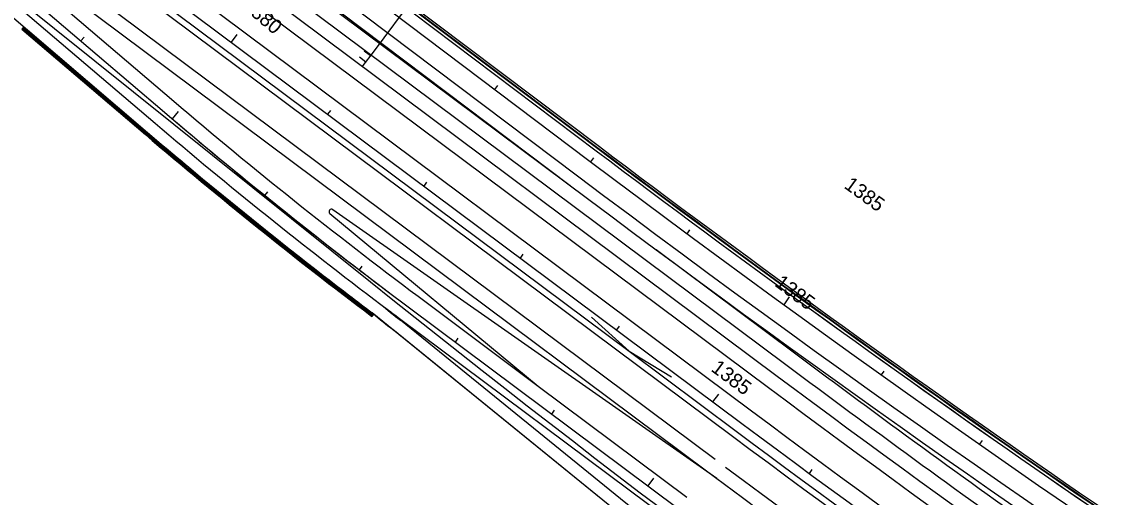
# Model space of a CAD drawing. Extents: x 2338610 to 2351914, y 366540 to 376484.
# Drawn here: x 2344700 to 2345613, y 370482 to 370877 of the extents above; entities that cross this region are included whole.
import ezdxf

# ---------------------------------------------------------------- set-up
doc = ezdxf.new("R2010")
doc.units = 0
for name, color, linetype in [('RD_HC_Cl', 7, 'Continuous'), ('RD_HC_CL_Rel', 7, 'Continuous'), ('RD_PD_Final_LnLine', 7, 'Continuous'), ('RD_PD_Final_TrvlWay', 7, 'Continuous'), ('RD_PD_GR', 7, 'Continuous'), ('RD_PD_MedBWall', 7, 'Continuous'), ('RD_PD_MedGR', 7, 'Continuous'), ('RD_PD_NOISE-WALL-GM', 7, 'Continuous'), ('RD_PD_PaveShd', 7, 'Continuous'), ('RD_PD_WallFill', 7, 'Continuous'), ('TR SN EXTRUDED PANEL SIGNS - GROUND MOUNTED', 7, 'Continuous'), ('TR SN UNASSIGNED 7', 7, 'Continuous')]:
    doc.layers.add(name, color=color, linetype=linetype)

msp = doc.modelspace()

# ---------------------------------------------------------------- linework, layer by layer
at = {"layer": 'RD_HC_Cl'}
for p, q in [((2339299.68, 375020.33), (2345298.75, 370542.85)), ((2344813.13, 371031.79), (2345171.51, 370761.65))]:
    msp.add_line(p, q, dxfattribs=at)
for centre, radius, start, end in [((2352034, 379865.62), 11400.7, 232.99132, 241.72492), ((2352152.85, 379726.19), 11459.16, 233.263715, 239.178507)]:
    msp.add_arc(centre, radius, start, end, dxfattribs=at)
at = {"layer": 'RD_HC_CL_Rel'}
for p, q in [((2344362.05, 371190.8), (2344818.24, 370801.72)), ((2345022.04, 370639.05), (2345245.86, 370471.99))]:
    msp.add_line(p, q, dxfattribs=at)
msp.add_arc((2347422.04, 373854.65), 4012.5, 229.5396, 233.26372, dxfattribs=at)
at = {"layer": 'RD_PD_Final_LnLine'}
for p, q in [((2344195, 371413.02), (2345320.98, 370572.63)), ((2344150.54, 371353.45), (2345276.52, 370513.06)), ((2344330.62, 371189.3), (2344989.66, 370660.63)), ((2344330.62, 371189.3), (2344989.66, 370660.63)), ((2344330.62, 371189.3), (2344989.66, 370660.63)), ((2344330.62, 371189.3), (2344989.66, 370660.63)), ((2344457.72, 371109.21), (2344818.24, 370801.72)), ((2344782.88, 370989.22), (2345328.15, 370582.25)), ((2345022.04, 370639.05), (2345245.86, 370471.99)), ((2345014.86, 370629.43), (2345238.68, 370462.38))]:
    msp.add_line(p, q, dxfattribs=at)
for centre, radius, start, end in [((2347422.04, 373854.65), 4012.5, 229.5396, 232.9704), ((2351872.76, 379241.01), 11000, 231.263715, 239.178507), ((2351872.76, 379241.01), 11000, 231.263715, 239.178507), ((2351872.76, 379241.01), 11000, 231.263715, 239.178507), ((2351872.76, 379241.01), 11000, 231.263715, 239.178507), ((2347422.04, 373854.65), 4024.5, 232.9704, 233.26372), ((2352152.85, 379726.19), 11409.99, 233.263715, 239.178507), ((2352152.85, 379726.19), 11421.99, 233.263715, 239.178507), ((2352152.85, 379726.19), 11496.33, 233.317765, 239.178507)]:
    msp.add_arc(centre, radius, start, end, dxfattribs=at)
at = {"layer": 'RD_PD_Final_TrvlWay'}
for p, q in [((2344450.23, 371099.83), (2344810.46, 370792.59)), ((2344813.13, 371031.79), (2345171.51, 370761.65)), ((2344803.5, 371019.02), (2345161.87, 370748.88)), ((2344605.78, 370998.71), (2345269.34, 370503.45)), ((2344605.78, 370998.71), (2344826.03, 370810.85)), ((2344790.37, 370998.61), (2345335.33, 370591.87)), ((2344955.88, 370717.43), (2345129.3, 370573.96)), ((2345278.04, 370496.96), (2344958.32, 370720.61)), ((2345029.21, 370648.67), (2345129.3, 370573.96)), ((2345231.51, 370452.76), (2345014.54, 370628.63)), ((2345129.3, 370573.96), (2345253.04, 370481.61))]:
    msp.add_line(p, q, dxfattribs=at)
for centre, radius, start, end in [((2347422.04, 373854.65), 4000.5, 229.5396, 233.26372), ((2347422.04, 373854.65), 4024.5, 229.5396, 232.9704), ((2352034, 379865.62), 11400.7, 232.99132, 241.724919), ((2352034, 379865.62), 11416.7, 232.99132, 241.724919), ((2344957.12, 370719.01), 2, 53.26372, 231.82922), ((2347578.46, 373791.82), 4071.79, 230.68024, 230.97356), ((2352152.85, 379726.19), 11397.99, 233.263715, 234.598626), ((2352152.85, 379726.19), 11508.33, 233.263715, 239.178507)]:
    msp.add_arc(centre, radius, start, end, dxfattribs=at)
at = {"layer": 'RD_PD_GR'}
msp.add_line((2345225.21, 370444.99), (2345008.24, 370620.86), dxfattribs=at)
msp.add_arc((2347578.46, 373791.82), 4081.79, 230.68024, 230.97356, dxfattribs=at)
at = {"layer": 'RD_PD_MedBWall'}
for p, q in [((2344467.41, 371072.03), (2344803.97, 370784.99)), ((2344820.56, 371041.64), (2345178.93, 370771.5)), ((2344819.15, 371039.78), (2345177.53, 370769.64)), ((2344701.11, 370872.71), (2344699.6, 370870.93)), ((2344700.47, 370871.95), (2344803.32, 370784.22)), ((2344992.36, 370633.81), (2344991.75, 370633.02))]:
    msp.add_line(p, q, dxfattribs=at)
for centre, radius, start, end in [((2347422.04, 373854.65), 4035.5, 229.5396, 232.9704), ((2347422.04, 373854.65), 4034.5, 229.5396, 232.9704), ((2352034, 379865.62), 11390.7, 232.99132, 237.523981), ((2352034, 379865.62), 11388.37, 232.99132, 237.523981)]:
    msp.add_arc(centre, radius, start, end, dxfattribs=at)
at = {"layer": 'RD_PD_MedGR'}
for p, q in [((2343635.7, 371774.1), (2345204.83, 370602.96)), ((2345173.57, 370631.28), (2345204.84, 370602.95)), ((2345204.84, 370602.95), (2345240.16, 370581.58)), ((2345204.84, 370602.95), (2345293.96, 370536.44))]:
    msp.add_line(p, q, dxfattribs=at)
msp.add_arc((2352152.85, 379726.19), 11467.16, 233.263715, 238.613636, dxfattribs=at)
at = {"layer": 'RD_PD_NOISE-WALL-GM'}
for p, q in [((2344820.86, 371042.04), (2345179.23, 370771.9)), ((2344821.76, 371043.24), (2345180.13, 370773.1))]:
    msp.add_line(p, q, dxfattribs=at)
for radius in [11387.87, 11386.37]:
    msp.add_arc((2352034, 379865.62), radius, 232.99132, 237.523981, dxfattribs=at)
at = {"layer": 'RD_PD_PaveShd'}
for p, q in [((2343761.92, 371706.31), (2345306.62, 370553.4)), ((2343847.56, 371609.53), (2345290.87, 370532.3)), ((2344467.41, 371072.03), (2344803.97, 370784.99)), ((2344819.15, 371039.78), (2345177.53, 370769.64)), ((2344797.47, 371008.28), (2345171.34, 370729.24)), ((2344797.48, 371011.03), (2345155.86, 370740.89)), ((2345227.35, 370687.44), (2345342.51, 370601.49)), ((2345225.36, 370444.86), (2344991, 370634.84))]:
    msp.add_line(p, q, dxfattribs=at)
for centre, radius, start, end in [((2347422.04, 373854.65), 4034.5, 229.5396, 232.94578), ((2352034, 379865.62), 11390.7, 232.99132, 237.52318), ((2352034, 379865.62), 11426.7, 233.088517, 240.436611), ((2352152.85, 379726.19), 11385.99, 233.263715, 234.598626), ((2352152.85, 379726.19), 11445.99, 233.263715, 239.178507), ((2352152.85, 379726.19), 11472.33, 233.263715, 239.178507)]:
    msp.add_arc(centre, radius, start, end, dxfattribs=at)
at = {"layer": 'RD_PD_WallFill'}
for p, q in [((2344699.49, 370870.8), (2344802.34, 370783.08)), ((2344699.82, 370871.18), (2344802.67, 370783.46)), ((2344700.14, 370871.56), (2344802.99, 370783.84)), ((2344700.47, 370871.95), (2344803.32, 370784.22)), ((2344991.75, 370633.02), (2344990.85, 370631.82))]:
    msp.add_line(p, q, dxfattribs=at)
for radius in [4037, 4036.5, 4036]:
    msp.add_arc((2347422.04, 373854.65), radius, 229.5396, 232.9704, dxfattribs=at)
at = {"layer": 'TR SN EXTRUDED PANEL SIGNS - GROUND MOUNTED'}
for p, q in [((2345075.65, 370964.01), (2344992.65, 370852.8)), ((2344992.65, 370852.8), (2344982.55, 370839.51)), ((2344984.34, 370852.79), (2344989.63, 370848.77)), ((2344980.45, 370847.67), (2344985.76, 370843.64))]:
    msp.add_line(p, q, dxfattribs=at)
at = {"layer": 'TR SN UNASSIGNED 7'}
for p, q in [((2344748.73, 370861.01), (2344751.32, 370864.06)), ((2344873.99, 370859.87), (2344878.78, 370866.28)), ((2345093.18, 370820.7), (2345095.58, 370823.89)), ((2344824.82, 370796.13), (2344830, 370802.23)), ((2344954.13, 370800.06), (2344956.53, 370803.26)), ((2345173.03, 370760.51), (2345175.44, 370763.7)), ((2345034.27, 370740.24), (2345036.67, 370743.45)), ((2344901.84, 370732.36), (2344904.35, 370735.47)), ((2345253.16, 370700.68), (2345255.54, 370703.89)), ((2345114.41, 370680.43), (2345116.81, 370683.63)), ((2344980.43, 370670.52), (2344982.86, 370673.7)), ((2345333.81, 370641.55), (2345338.51, 370648.02)), ((2345194.55, 370620.62), (2345196.95, 370623.82)), ((2345060.37, 370610.44), (2345062.76, 370613.65)), ((2345414.97, 370583.14), (2345417.29, 370586.39)), ((2345274.69, 370560.8), (2345279.48, 370567.21)), ((2345140.51, 370550.63), (2345142.9, 370553.83)), ((2345496.64, 370525.44), (2345498.94, 370528.71)), ((2345354.96, 370501.16), (2345357.33, 370504.38)), ((2345220.65, 370490.81), (2345225.43, 370497.22))]:
    msp.add_line(p, q, dxfattribs=at)

# ---------------------------------------------------------------- texts
for s, rotation, p in [('1380', 319.6629, (2344882.43, 370888.89)), ('1385', 324.00604, (2345383.09, 370739.24)), ('1385', 323.26372, (2345325.24, 370657.84)), ('1385', 323.26372, (2345272.33, 370587.01))]:
    msp.add_text(s, height=12, rotation=rotation, dxfattribs=at).set_placement(p)

doc.saveas('drawing.dxf')
